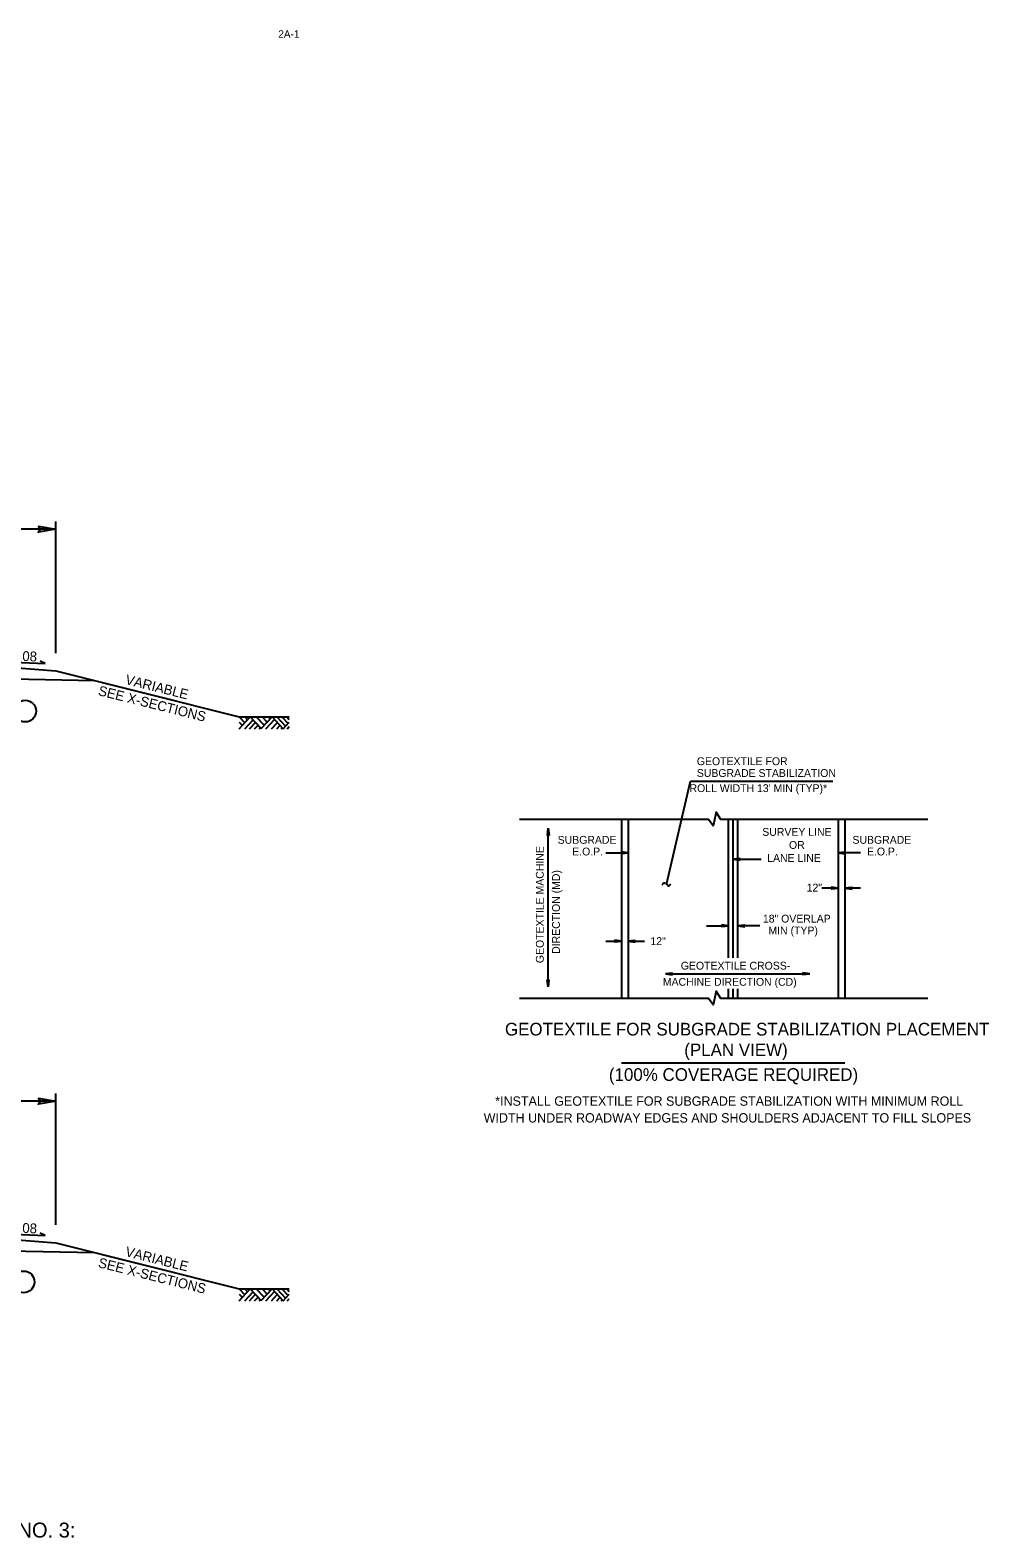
# Model space of a CAD drawing. Extents: x 1901582 to 1902252, y 193723 to 194156.
# Drawn here: x 1902110.9 to 1902174.9, y 194054.6 to 194155.2 of the extents above; entities that cross this region are included whole.
import ezdxf

# ---------------------------------------------------------------- set-up
doc = ezdxf.new("R2010")
doc.units = 0
for name, color, linetype in [('Old_Level_1', 7, 'Continuous'), ('Old_Level_11', 7, 'Continuous'), ('Old_Level_2', 7, 'Continuous'), ('Old_Level_44', 7, 'Continuous'), ('Prop Dimension Text', 7, 'Continuous'), ('Typical Pavement Slope Information CELL', 7, 'Continuous'), ('Typical Terminator CELL', 7, 'Continuous')]:
    doc.layers.add(name, color=color, linetype=linetype)

msp = doc.modelspace()

# ---------------------------------------------------------------- linework, layer by layer
at = {"layer": 'Old_Level_1'}
for p, q in [((1902112.59, 194121.92), (1902104.59, 194121.92)), ((1902112.59, 194113.64), (1902112.59, 194122.42)), ((1902108.59, 194112.77), (1902112.59, 194112.45)), ((1902088.59, 194112.34), (1902115.17, 194111.8)), ((1902112.59, 194112.45), (1902120.59, 194110.45)), ((1902112.59, 194112.45), (1902124.83, 194109.39)), ((1902112.59, 194083.73), (1902104.59, 194083.73)), ((1902112.59, 194075.48), (1902112.59, 194084.23)), ((1902108.59, 194074.58), (1902112.59, 194074.26)), ((1902109.44, 194073.73), (1902115.17, 194073.62)), ((1902112.59, 194074.26), (1902120.59, 194072.26)), ((1902112.59, 194074.26), (1902124.83, 194071.2))]:
    msp.add_line(p, q, dxfattribs=at)
for points in [[(1902124.83, 194109.39), (1902128.17, 194109.39)], [(1902124.83, 194071.2), (1902128.17, 194071.2)]]:
    msp.add_lwpolyline(points, dxfattribs=at)
at = {"layer": 'Old_Level_11'}
for p, q in [((1902124.83, 194109.39), (1902125.2, 194108.99)), ((1902124.83, 194108.58), (1902125.57, 194109.38)), ((1902124.83, 194109.03), (1902125.04, 194108.8)), ((1902125.2, 194109.39), (1902125.39, 194109.19)), ((1902125.2, 194108.58), (1902125.76, 194109.18)), ((1902125.51, 194108.58), (1902125.91, 194109.01)), ((1902125.57, 194109.38), (1902126.3, 194108.6)), ((1902125.86, 194108.58), (1902126.09, 194108.83)), ((1902125.96, 194109.39), (1902126.5, 194108.82)), ((1902126.17, 194108.58), (1902126.24, 194108.66)), ((1902126.3, 194108.6), (1902127.03, 194109.39)), ((1902126.36, 194109.39), (1902126.69, 194109.03)), ((1902126.61, 194108.58), (1902127.19, 194109.21)), ((1902126.76, 194109.39), (1902126.9, 194109.25)), ((1902126.98, 194108.58), (1902127.38, 194109.01)), ((1902127.03, 194109.39), (1902127.77, 194108.59)), ((1902127.34, 194108.58), (1902127.56, 194108.82)), ((1902127.35, 194109.39), (1902127.93, 194108.77)), ((1902127.64, 194108.58), (1902127.71, 194108.66)), ((1902127.68, 194109.39), (1902128.1, 194108.94)), ((1902127.77, 194108.59), (1902128.17, 194109.03)), ((1902128, 194109.39), (1902128.17, 194109.21)), ((1902128.04, 194108.58), (1902128.17, 194108.73)), ((1902124.83, 194071.2), (1902125.2, 194070.8)), ((1902124.83, 194070.4), (1902125.57, 194071.19)), ((1902124.83, 194070.84), (1902125.04, 194070.62)), ((1902125.2, 194071.2), (1902125.39, 194071)), ((1902125.2, 194070.4), (1902125.76, 194070.99)), ((1902125.51, 194070.4), (1902125.91, 194070.83)), ((1902125.57, 194071.19), (1902126.3, 194070.41)), ((1902125.86, 194070.4), (1902126.09, 194070.64)), ((1902125.96, 194071.2), (1902126.5, 194070.63)), ((1902126.17, 194070.4), (1902126.24, 194070.47)), ((1902126.3, 194070.41), (1902127.03, 194071.2)), ((1902126.36, 194071.2), (1902126.69, 194070.84)), ((1902126.61, 194070.4), (1902127.19, 194071.02)), ((1902126.76, 194071.2), (1902126.9, 194071.06)), ((1902126.98, 194070.4), (1902127.38, 194070.83)), ((1902127.03, 194071.2), (1902127.77, 194070.4)), ((1902127.34, 194070.4), (1902127.56, 194070.63)), ((1902127.35, 194071.2), (1902127.93, 194070.58)), ((1902127.64, 194070.4), (1902127.71, 194070.47)), ((1902127.68, 194071.2), (1902128.1, 194070.76)), ((1902127.77, 194070.4), (1902128.17, 194070.84)), ((1902128, 194071.2), (1902128.17, 194071.02)), ((1902128.04, 194070.4), (1902128.17, 194070.54))]:
    msp.add_line(p, q, dxfattribs=at)
for centre in [(1902110.54, 194109.77), (1902110.44, 194071.66)]:
    msp.add_circle(centre, 0.725, dxfattribs=at)
at = {"layer": 'Prop Dimension Text'}
for p, q in [((1902153.36, 194098.2), (1902154.95, 194105.09)), ((1902154.95, 194105.09), (1902164.45, 194105.09)), ((1902145.45, 194101.94), (1902145.39, 194101.47)), ((1902145.4, 194101.48), (1902145.45, 194101.94)), ((1902145.45, 194101.94), (1902145.41, 194101.48)), ((1902145.42, 194101.49), (1902145.45, 194101.94)), ((1902145.45, 194101.94), (1902145.43, 194101.5)), ((1902145.43, 194101.51), (1902145.45, 194101.94)), ((1902145.45, 194101.94), (1902145.44, 194101.52)), ((1902145.45, 194101.94), (1902145.52, 194101.47)), ((1902145.45, 194101.53), (1902145.45, 194101.94)), ((1902145.46, 194101.52), (1902145.45, 194101.94)), ((1902145.45, 194101.94), (1902145.47, 194101.51)), ((1902145.48, 194101.5), (1902145.45, 194101.94)), ((1902145.45, 194101.94), (1902145.49, 194101.49)), ((1902145.5, 194101.48), (1902145.45, 194101.94)), ((1902145.45, 194101.94), (1902145.51, 194101.48)), ((1902145.45, 194091.35), (1902145.45, 194101.94)), ((1902150.35, 194102.53), (1902150.35, 194090.58)), ((1902150.8, 194102.53), (1902150.8, 194090.58)), ((1902157.49, 194093.29), (1902157.49, 194102.53)), ((1902157.81, 194093.29), (1902157.81, 194102.53)), ((1902158.12, 194093.29), (1902158.12, 194102.53)), ((1902164.82, 194102.53), (1902164.82, 194090.58)), ((1902165.26, 194102.53), (1902165.26, 194090.58)), ((1902145.39, 194101.47), (1902145.45, 194101.53)), ((1902145.45, 194101.53), (1902145.52, 194101.47)), ((1902149.31, 194100.3), (1902150.8, 194100.3)), ((1902150.8, 194100.3), (1902150.32, 194100.36)), ((1902150.32, 194100.36), (1902150.39, 194100.3)), ((1902150.8, 194100.3), (1902150.32, 194100.23)), ((1902150.39, 194100.3), (1902150.32, 194100.23)), ((1902150.33, 194100.35), (1902150.8, 194100.3)), ((1902150.8, 194100.3), (1902150.33, 194100.24)), ((1902150.8, 194100.3), (1902150.34, 194100.34)), ((1902150.34, 194100.25), (1902150.8, 194100.3)), ((1902150.35, 194100.34), (1902150.8, 194100.3)), ((1902150.8, 194100.3), (1902150.35, 194100.26)), ((1902150.8, 194100.3), (1902150.36, 194100.33)), ((1902150.36, 194100.27), (1902150.8, 194100.3)), ((1902150.37, 194100.32), (1902150.8, 194100.3)), ((1902150.8, 194100.3), (1902150.37, 194100.28)), ((1902150.8, 194100.3), (1902150.38, 194100.31)), ((1902150.38, 194100.29), (1902150.8, 194100.3)), ((1902150.39, 194100.3), (1902150.8, 194100.3)), ((1902157.81, 194099.89), (1902158.28, 194099.95)), ((1902157.81, 194099.89), (1902158.27, 194099.94)), ((1902157.81, 194099.89), (1902158.25, 194099.93)), ((1902158.26, 194099.93), (1902157.81, 194099.89)), ((1902158.24, 194099.92), (1902157.81, 194099.89)), ((1902157.81, 194099.89), (1902158.24, 194099.91)), ((1902158.23, 194099.9), (1902157.81, 194099.89)), ((1902157.81, 194099.89), (1902158.28, 194099.82)), ((1902158.27, 194099.83), (1902157.81, 194099.89)), ((1902157.81, 194099.89), (1902158.26, 194099.84)), ((1902158.25, 194099.85), (1902157.81, 194099.89)), ((1902157.81, 194099.89), (1902158.24, 194099.86)), ((1902158.24, 194099.87), (1902157.81, 194099.89)), ((1902157.81, 194099.89), (1902158.23, 194099.88)), ((1902158.22, 194099.89), (1902157.81, 194099.89)), ((1902157.81, 194099.89), (1902159.68, 194099.89)), ((1902158.22, 194099.89), (1902158.28, 194099.95)), ((1902158.28, 194099.82), (1902158.22, 194099.89)), ((1902164.82, 194100.3), (1902165.29, 194100.36)), ((1902165.28, 194100.35), (1902164.82, 194100.3)), ((1902164.82, 194100.3), (1902165.27, 194100.34)), ((1902165.26, 194100.34), (1902164.82, 194100.3)), ((1902164.82, 194100.3), (1902165.25, 194100.33)), ((1902165.25, 194100.32), (1902164.82, 194100.3)), ((1902164.82, 194100.3), (1902165.24, 194100.31)), ((1902166.3, 194100.3), (1902164.82, 194100.3)), ((1902164.82, 194100.3), (1902165.29, 194100.23)), ((1902165.23, 194100.3), (1902164.82, 194100.3)), ((1902165.24, 194100.29), (1902164.82, 194100.3)), ((1902164.82, 194100.3), (1902165.25, 194100.28)), ((1902165.25, 194100.27), (1902164.82, 194100.3)), ((1902164.82, 194100.3), (1902165.26, 194100.26)), ((1902165.27, 194100.25), (1902164.82, 194100.3)), ((1902164.82, 194100.3), (1902165.28, 194100.24)), ((1902165.29, 194100.36), (1902165.23, 194100.3)), ((1902165.23, 194100.3), (1902165.29, 194100.23)), ((1902153.07, 194098.17), (1902153.1, 194098.21)), ((1902153.28, 194098.25), (1902153.44, 194098.14)), ((1902153.6, 194098.18), (1902153.64, 194098.24)), ((1902164.82, 194097.95), (1902163.72, 194097.95)), ((1902164.82, 194097.95), (1902164.34, 194098.01)), ((1902164.41, 194097.95), (1902164.34, 194098.01)), ((1902164.82, 194097.95), (1902164.34, 194097.88)), ((1902164.34, 194097.88), (1902164.41, 194097.95)), ((1902164.82, 194097.95), (1902164.35, 194098)), ((1902164.35, 194097.89), (1902164.82, 194097.95)), ((1902164.36, 194097.99), (1902164.82, 194097.95)), ((1902164.82, 194097.95), (1902164.36, 194097.9)), ((1902164.82, 194097.95), (1902164.37, 194097.98)), ((1902164.37, 194097.91), (1902164.82, 194097.95)), ((1902164.38, 194097.97), (1902164.82, 194097.95)), ((1902164.82, 194097.95), (1902164.38, 194097.92)), ((1902164.82, 194097.95), (1902164.39, 194097.96)), ((1902164.39, 194097.93), (1902164.82, 194097.95)), ((1902164.4, 194097.96), (1902164.82, 194097.95)), ((1902164.82, 194097.95), (1902164.4, 194097.94)), ((1902164.41, 194097.95), (1902164.82, 194097.95)), ((1902165.26, 194097.95), (1902165.74, 194098.01)), ((1902165.73, 194098), (1902165.26, 194097.95)), ((1902165.26, 194097.95), (1902165.72, 194097.99)), ((1902165.71, 194097.98), (1902165.26, 194097.95)), ((1902165.26, 194097.95), (1902165.7, 194097.97)), ((1902165.69, 194097.97), (1902165.26, 194097.95)), ((1902165.26, 194097.95), (1902165.68, 194097.96)), ((1902166.3, 194097.95), (1902165.26, 194097.95)), ((1902165.26, 194097.95), (1902165.74, 194097.88)), ((1902165.67, 194097.95), (1902165.26, 194097.95)), ((1902165.68, 194097.94), (1902165.26, 194097.95)), ((1902165.26, 194097.95), (1902165.69, 194097.93)), ((1902165.7, 194097.92), (1902165.26, 194097.95)), ((1902165.26, 194097.95), (1902165.71, 194097.91)), ((1902165.72, 194097.9), (1902165.26, 194097.95)), ((1902165.26, 194097.95), (1902165.73, 194097.89)), ((1902165.74, 194098.01), (1902165.67, 194097.95)), ((1902165.67, 194097.95), (1902165.74, 194097.88)), ((1902156.02, 194095.43), (1902157.49, 194095.43)), ((1902157.49, 194095.43), (1902157.02, 194095.5)), ((1902157.02, 194095.5), (1902157.08, 194095.43)), ((1902157.49, 194095.43), (1902157.02, 194095.37)), ((1902157.08, 194095.43), (1902157.02, 194095.37)), ((1902157.03, 194095.49), (1902157.49, 194095.43)), ((1902157.49, 194095.43), (1902157.03, 194095.38)), ((1902157.49, 194095.43), (1902157.04, 194095.48)), ((1902157.04, 194095.39), (1902157.49, 194095.43)), ((1902157.05, 194095.47), (1902157.49, 194095.43)), ((1902157.49, 194095.43), (1902157.05, 194095.4)), ((1902157.49, 194095.43), (1902157.06, 194095.46)), ((1902157.06, 194095.41), (1902157.49, 194095.43)), ((1902157.07, 194095.45), (1902157.49, 194095.43)), ((1902157.49, 194095.43), (1902157.07, 194095.44)), ((1902157.07, 194095.42), (1902157.49, 194095.43)), ((1902157.49, 194095.43), (1902157.07, 194095.41)), ((1902157.08, 194095.43), (1902157.49, 194095.43)), ((1902158.12, 194095.43), (1902158.59, 194095.5)), ((1902158.12, 194095.43), (1902158.58, 194095.49)), ((1902158.57, 194095.48), (1902158.12, 194095.43)), ((1902158.12, 194095.43), (1902158.56, 194095.47)), ((1902158.56, 194095.46), (1902158.12, 194095.43)), ((1902158.12, 194095.43), (1902158.55, 194095.45)), ((1902158.54, 194095.44), (1902158.12, 194095.43)), ((1902158.12, 194095.43), (1902158.59, 194095.37)), ((1902158.58, 194095.38), (1902158.12, 194095.43)), ((1902158.12, 194095.43), (1902158.57, 194095.39)), ((1902158.56, 194095.4), (1902158.12, 194095.43)), ((1902158.12, 194095.43), (1902158.56, 194095.41)), ((1902158.55, 194095.41), (1902158.12, 194095.43)), ((1902158.12, 194095.43), (1902158.54, 194095.42)), ((1902158.53, 194095.43), (1902158.12, 194095.43)), ((1902159.59, 194095.43), (1902158.12, 194095.43)), ((1902158.53, 194095.43), (1902158.59, 194095.5)), ((1902158.59, 194095.37), (1902158.53, 194095.43)), ((1902149.31, 194094.41), (1902150.35, 194094.41)), ((1902150.35, 194094.41), (1902149.88, 194094.47)), ((1902149.88, 194094.47), (1902149.94, 194094.41)), ((1902150.35, 194094.41), (1902149.88, 194094.34)), ((1902149.94, 194094.41), (1902149.88, 194094.34)), ((1902149.89, 194094.46), (1902150.35, 194094.41)), ((1902150.35, 194094.41), (1902149.89, 194094.35)), ((1902150.35, 194094.41), (1902149.9, 194094.45)), ((1902149.9, 194094.44), (1902150.35, 194094.41)), ((1902150.35, 194094.41), (1902149.9, 194094.37)), ((1902149.9, 194094.36), (1902150.35, 194094.41)), ((1902150.35, 194094.41), (1902149.91, 194094.43)), ((1902149.91, 194094.38), (1902150.35, 194094.41)), ((1902149.92, 194094.43), (1902150.35, 194094.41)), ((1902150.35, 194094.41), (1902149.92, 194094.39)), ((1902150.35, 194094.41), (1902149.93, 194094.42)), ((1902149.93, 194094.4), (1902150.35, 194094.41)), ((1902149.94, 194094.41), (1902150.35, 194094.41)), ((1902150.8, 194094.41), (1902151.27, 194094.47)), ((1902150.8, 194094.41), (1902151.26, 194094.46)), ((1902151.25, 194094.45), (1902150.8, 194094.41)), ((1902150.8, 194094.41), (1902151.24, 194094.44)), ((1902151.23, 194094.43), (1902150.8, 194094.41)), ((1902151.22, 194094.42), (1902150.8, 194094.41)), ((1902150.8, 194094.41), (1902151.23, 194094.42)), ((1902150.8, 194094.41), (1902151.89, 194094.41)), ((1902150.8, 194094.41), (1902151.27, 194094.34)), ((1902151.26, 194094.35), (1902150.8, 194094.41)), ((1902150.8, 194094.41), (1902151.25, 194094.36)), ((1902151.24, 194094.37), (1902150.8, 194094.41)), ((1902150.8, 194094.41), (1902151.23, 194094.38)), ((1902151.23, 194094.39), (1902150.8, 194094.41)), ((1902150.8, 194094.41), (1902151.22, 194094.4)), ((1902151.21, 194094.41), (1902150.8, 194094.41)), ((1902151.21, 194094.41), (1902151.27, 194094.47)), ((1902151.27, 194094.34), (1902151.21, 194094.41)), ((1902145.45, 194091.35), (1902145.39, 194091.83)), ((1902145.45, 194091.77), (1902145.39, 194091.83)), ((1902145.45, 194091.35), (1902145.4, 194091.82)), ((1902145.41, 194091.81), (1902145.45, 194091.35)), ((1902145.45, 194091.35), (1902145.42, 194091.8)), ((1902145.43, 194091.79), (1902145.45, 194091.35)), ((1902145.45, 194091.35), (1902145.44, 194091.78)), ((1902145.44, 194091.77), (1902145.45, 194091.35)), ((1902145.45, 194091.35), (1902145.52, 194091.83)), ((1902145.52, 194091.83), (1902145.45, 194091.77)), ((1902145.51, 194091.82), (1902145.45, 194091.35)), ((1902145.45, 194091.35), (1902145.5, 194091.81)), ((1902145.49, 194091.8), (1902145.45, 194091.35)), ((1902145.45, 194091.35), (1902145.48, 194091.79)), ((1902145.47, 194091.78), (1902145.45, 194091.35)), ((1902145.45, 194091.35), (1902145.46, 194091.77)), ((1902145.45, 194091.77), (1902145.45, 194091.35)), ((1902153.28, 194092.23), (1902153.75, 194092.3)), ((1902153.28, 194092.23), (1902153.74, 194092.29)), ((1902153.74, 194092.28), (1902153.28, 194092.23)), ((1902153.28, 194092.23), (1902153.73, 194092.27)), ((1902153.72, 194092.26), (1902153.28, 194092.23)), ((1902153.28, 194092.23), (1902153.71, 194092.25)), ((1902153.7, 194092.24), (1902153.28, 194092.23)), ((1902153.28, 194092.23), (1902153.75, 194092.17)), ((1902153.74, 194092.18), (1902153.28, 194092.23)), ((1902153.28, 194092.23), (1902153.74, 194092.19)), ((1902153.73, 194092.2), (1902153.28, 194092.23)), ((1902153.28, 194092.23), (1902153.72, 194092.21)), ((1902153.71, 194092.21), (1902153.28, 194092.23)), ((1902153.28, 194092.23), (1902153.7, 194092.22)), ((1902153.69, 194092.23), (1902153.28, 194092.23)), ((1902153.28, 194092.23), (1902162.92, 194092.23)), ((1902153.69, 194092.23), (1902153.75, 194092.3)), ((1902153.75, 194092.17), (1902153.69, 194092.23)), ((1902162.92, 194092.23), (1902162.44, 194092.3)), ((1902162.44, 194092.3), (1902162.5, 194092.23)), ((1902162.92, 194092.23), (1902162.44, 194092.17)), ((1902162.5, 194092.23), (1902162.44, 194092.17)), ((1902162.45, 194092.29), (1902162.92, 194092.23)), ((1902162.92, 194092.23), (1902162.45, 194092.18)), ((1902162.92, 194092.23), (1902162.46, 194092.28)), ((1902162.46, 194092.19), (1902162.92, 194092.23)), ((1902162.47, 194092.27), (1902162.92, 194092.23)), ((1902162.92, 194092.23), (1902162.47, 194092.19)), ((1902162.92, 194092.23), (1902162.48, 194092.26)), ((1902162.48, 194092.2), (1902162.92, 194092.23)), ((1902162.49, 194092.25), (1902162.92, 194092.23)), ((1902162.92, 194092.23), (1902162.49, 194092.21)), ((1902162.92, 194092.23), (1902162.5, 194092.24)), ((1902162.5, 194092.23), (1902162.92, 194092.23)), ((1902162.5, 194092.22), (1902162.92, 194092.23)), ((1902157.49, 194090.58), (1902157.49, 194091.22)), ((1902157.81, 194090.58), (1902157.81, 194091.22)), ((1902158.12, 194090.58), (1902158.12, 194091.22)), ((1902150.35, 194086.29), (1902165.26, 194086.29))]:
    msp.add_line(p, q, dxfattribs=at)
for points in [[(1902170.79, 194102.53), (1902156.98, 194102.53), (1902156.67, 194103.02), (1902156.48, 194102.11), (1902156.16, 194102.53), (1902143.55, 194102.53)], [(1902170.79, 194090.58), (1902156.98, 194090.58), (1902156.67, 194091.07), (1902156.48, 194090.16), (1902156.16, 194090.58), (1902143.55, 194090.58)]]:
    msp.add_lwpolyline(points, dxfattribs=at)
for centre, radius, start, end in [((1902153.2, 194098.17), 0.114, 48.0321, 157.831), ((1902153.51, 194098.21), 0.101, 230.477, 338.7625)]:
    msp.add_arc(centre, radius, start, end, dxfattribs=at)
at = {"layer": 'Typical Pavement Slope Information CELL'}
for p, q in [((1902109.28, 194113.05), (1902111.87, 194112.94)), ((1902111.87, 194112.94), (1902111.54, 194113.11)), ((1902109.28, 194074.86), (1902111.87, 194074.75)), ((1902111.87, 194074.75), (1902111.54, 194074.92))]:
    msp.add_line(p, q, dxfattribs=at)
at = {"layer": 'Typical Terminator CELL'}
for points in [[(1902111.41, 194122.12), (1902112.59, 194121.92), (1902111.41, 194121.71), (1902111.56, 194121.92)], [(1902111.41, 194083.93), (1902112.59, 194083.73), (1902111.41, 194083.52), (1902111.56, 194083.73)]]:
    msp.add_lwpolyline(points, close=True, dxfattribs=at)

# ---------------------------------------------------------------- texts
at = {"layer": 'Old_Level_1'}
for s, p in [('VARIABLE', (1902117.18, 194111.58)), ('SEE X-SECTIONS', (1902115.37, 194110.84)), ('VARIABLE', (1902117.18, 194073.39)), ('SEE X-SECTIONS', (1902115.37, 194072.65))]:
    msp.add_text(s, height=0.656, rotation=345.9638, dxfattribs=at).set_placement(p)
at = {"layer": 'Old_Level_11'}
msp.add_text('TRANSITION FROM TYPICAL SECTION NO. 2 TO TYPICAL SECTION NO. 3: ', height=1, dxfattribs=at).set_placement((1902066.64, 194054.59))
at = {"layer": 'Old_Level_2'}
for p in [(1902109.61, 194113.15), (1902109.61, 194074.97)]:
    msp.add_text('0.08', height=0.656, rotation=357.4644, dxfattribs=at).set_placement(p)
at = {"layer": 'Old_Level_44'}
msp.add_text('2A-1', height=0.5, dxfattribs=at).set_placement((1902127.44, 194154.72))
at = {"layer": 'Prop Dimension Text'}
for s, height, p in [('GEOTEXTILE FOR', 0.5229, (1902155.38, 194106.16)), ('SUBGRADE STABILIZATION', 0.5229, (1902155.38, 194105.37)), ("ROLL WIDTH 13' MIN (TYP)*", 0.5229, (1902154.89, 194104.36)), ('SURVEY LINE', 0.5229, (1902159.75, 194101.44)), ('SUBGRADE', 0.523, (1902146.09, 194100.91)), ('E.O.P.', 0.523, (1902147.06, 194100.13)), ('OR', 0.523, (1902161.53, 194100.57)), ('SUBGRADE', 0.523, (1902165.77, 194100.91)), ('E.O.P.', 0.523, (1902166.74, 194100.13)), ('LANE LINE', 0.523, (1902160.08, 194099.7)), ('12"', 0.523, (1902162.71, 194097.72)), ('18" OVERLAP', 0.5229, (1902159.79, 194095.65)), ('12"', 0.523, (1902152.28, 194094.15)), ('MIN (TYP)', 0.523, (1902160.16, 194094.86)), ('GEOTEXTILE CROSS-', 0.5229, (1902154.31, 194092.51)), ('MACHINE DIRECTION (CD)', 0.5229, (1902153.11, 194091.43)), ('GEOTEXTILE FOR SUBGRADE STABILIZATION PLACEMENT', 0.845, (1902142.57, 194088.11)), ('(PLAN VIEW)', 0.845, (1902154.54, 194086.73)), ('(100% COVERAGE REQUIRED)', 0.845, (1902149.51, 194085.08)), ('*INSTALL GEOTEXTILE FOR SUBGRADE STABILIZATION WITH MINIMUM ROLL', 0.6239, (1902141.92, 194083.42)), ('WIDTH UNDER ROADWAY EDGES AND SHOULDERS ADJACENT TO FILL SLOPES', 0.6239, (1902141.15, 194082.3))]:
    msp.add_text(s, height=height, dxfattribs=at).set_placement(p)
for s, p in [('GEOTEXTILE MACHINE', (1902145.16, 194092.94)), ('DIRECTION (MD)', (1902146.24, 194093.56))]:
    msp.add_text(s, height=0.5229, rotation=90, dxfattribs=at).set_placement(p)

doc.saveas('drawing.dxf')
